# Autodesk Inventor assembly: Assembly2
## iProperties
Shininess: 64.0
Length Units: 11269
Angle Units: 11279
Time Units: 11290
Mass Units: 11283
Length Display Precision: 3
Angle Display Precision: 2
Compacted: True
Created: 2004-07
Part Number: Assembly2
Document SubType Name: Assembly
Designer: John Blackburn
Manufacturer: Standard
Standards Organization: Custom
Density: 0.0
Volumn: 0.0
Area: 0.0
PropertySet Name: Model Information
Control State: 0
Master: False
Checked Out: False
Author: John Blackburn
